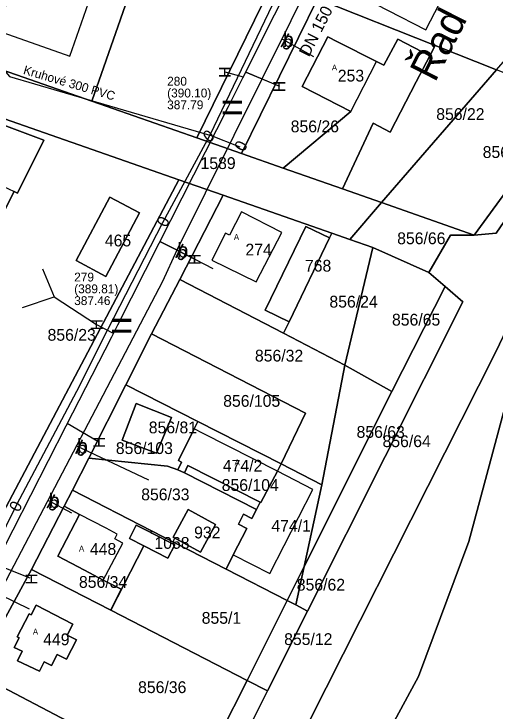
# Model space of a CAD drawing. Extents: x -564940 to -564406, y -1066466 to -1066072.
# Drawn here: x -564629.6 to -564548.1, y -1066405.8 to -1066287.6 of the extents above; entities that cross this region are included whole.
import ezdxf

# ---------------------------------------------------------------- set-up
doc = ezdxf.new("R2010")
doc.units = 0
for name, color, linetype in [('ft_g_5211', 7, 'Continuous'), ('ft_g_5411', 7, 'Continuous'), ('ft_g_6031', 7, 'Continuous'), ('ft_g_6040', 7, 'Continuous'), ('ft_g_6101', 7, 'Continuous'), ('ft_g_6101_ft_g_6101_da_6108_gtc_da_6108', 7, 'Continuous'), ('ft_g_6220', 7, 'Continuous'), ('ft_g_gps_soupe_pri', 7, 'Continuous'), ('ft_g_stoka', 7, 'Continuous'), ('ft_g_stoka_ft_g_stoka_da_popis_gtc_da_6004', 7, 'Continuous'), ('ft_g_vrad', 7, 'Continuous'), ('ft_g_vrad_ft_g_vrad_da_oznaceni_gtc_da_5095', 7, 'Continuous'), ('ft_g_vrad_ft_g_vrad_da_popis_gtc_da_5091', 7, 'Continuous'), ('ft_parcela_polygon', 7, 'Continuous'), ('ft_parcela_text', 7, 'Continuous'), ('ft_stavebni_objekt_bod', 7, 'Continuous'), ('ft_stavebni_objekt_polygon', 7, 'Continuous')]:
    doc.layers.add(name, color=color, linetype=linetype)

msp = doc.modelspace()

# ---------------------------------------------------------------- linework, layer by layer
at = {"layer": 'ft_g_5211'}
msp.add_line((-564623.9, -1066370.03), (-564619.9, -1066372.22), dxfattribs=at)
for points in [[(-564584.22, -1066291.86), (-564584.04, -1066291.96), (-564578.89, -1066294.81)], [(-564602.02, -1066327.63), (-564601.93, -1066327.68), (-564595.94, -1066330.79)], [(-564619.09, -1066360.83), (-564618.93, -1066360.91), (-564606.85, -1066366.6)], [(-564632.26, -1066385.97), (-564632.08, -1066386.06), (-564627.08, -1066388.46)]]:
    msp.add_lwpolyline(points, dxfattribs=at)
at = {"layer": 'ft_g_6040'}
for p, q in [((-564593.9, -1066297.43), (-564590.79, -1066298.28)), ((-564593.66, -1066297.5), (-564590.79, -1066298.28)), ((-564584.9, -1066299.77), (-564590.37, -1066297.46)), ((-564590.37, -1066297.46), (-564584.67, -1066299.87)), ((-564599.23, -1066329.07), (-564604.92, -1066326.21)), ((-564604.92, -1066326.21), (-564599.01, -1066329.18)), ((-564624.81, -1066330.81), (-564622.81, -1066335.57)), ((-564615.44, -1066360.1), (-564620.65, -1066357.07)), ((-564626.91, -1066383.3), (-564632.85, -1066380.93))]:
    msp.add_line(p, q, dxfattribs=at)
msp.add_lwpolyline([(-564628.19, -1066337.36), (-564622.81, -1066335.57), (-564615.63, -1066340.26), (-564612.81, -1066341.76)], dxfattribs=at)
at = {"layer": 'ft_g_stoka'}
msp.add_line((-564591.31, -1066310.22), (-564596.46, -1066308.15), dxfattribs=at)
for points in [[(-564553.41, -1066163.16), (-564553.48, -1066166.31), (-564548.89, -1066191.56), (-564549.63, -1066201.37), (-564551.36, -1066210.53), (-564553.55, -1066218.37), (-564556.52, -1066226.67), (-564558.83, -1066231.76), (-564567.86, -1066249.71), (-564582.71, -1066279.41), (-564586.53, -1066287.4), (-564596.46, -1066308.15), (-564604.5, -1066323.01), (-564613.83, -1066341.28), (-564619.05, -1066351.65), (-564629.23, -1066370.83), (-564638.15, -1066388.86), (-564652.7, -1066417.07), (-564664.74, -1066439.37), (-564677.25, -1066462.42), (-564679.03, -1066465.63)], [(-564574.81, -1066266.41), (-564590.9, -1066298.5), (-564591.23, -1066299.17), (-564593.34, -1066303.37)], [(-564636.43, -1066291.04), (-564630.4, -1066298.19), (-564613.43, -1066303.21), (-564596.46, -1066308.15)], [(-564593.34, -1066303.37), (-564605.08, -1066326.52), (-564612.1, -1066340.36)], [(-564612.1, -1066340.36), (-564613.14, -1066342.39), (-564620.85, -1066357.48), (-564632.88, -1066381), (-564633.79, -1066382.77)]]:
    msp.add_lwpolyline(points, dxfattribs=at)
at = {"layer": 'ft_g_vrad'}
msp.add_lwpolyline([(-564573.05, -1066269.82), (-564574.29, -1066272.32), (-564577.91, -1066279.06), (-564602.05, -1066327.68), (-564604.48, -1066332.96), (-564632.28, -1066386.02), (-564638.67, -1066398.97), (-564652.45, -1066423.53), (-564669.32, -1066454.46), (-564675.34, -1066465.63)], dxfattribs=at)
at = {"layer": 'ft_parcela_polygon'}
for points in [[(-564506.93, -1066072.02), (-564500.76, -1066095.62), (-564490.54, -1066131.29), (-564485.08, -1066150.07), (-564474.86, -1066195.24), (-564468.44, -1066228.77), (-564474.86, -1066248.97), (-564479.58, -1066256.49), (-564510.51, -1066292.89), (-564526.05, -1066309.43), (-564540.77, -1066329.78), (-564548.05, -1066345), (-564588.23, -1066424.58), (-564607.75, -1066462.97), (-564609.27, -1066465.63)], [(-564609.27, -1066465.63), (-564607.75, -1066462.97), (-564588.23, -1066424.58), (-564548.05, -1066345), (-564540.77, -1066329.78), (-564526.05, -1066309.43), (-564510.51, -1066292.89), (-564479.58, -1066256.49), (-564474.86, -1066248.97), (-564468.44, -1066228.77), (-564474.86, -1066195.24), (-564485.08, -1066150.07), (-564490.54, -1066131.29), (-564500.76, -1066095.62), (-564506.93, -1066072.02)], [(-564600.77, -1066465.63), (-564576.34, -1066428.17), (-564561.1, -1066399.98), (-564552.57, -1066377.06), (-564544.46, -1066346.76), (-564506.9, -1066296.8), (-564477.41, -1066257.73), (-564467.26, -1066239.44), (-564459.83, -1066220.33), (-564457.63, -1066204.67), (-564458.61, -1066193.4), (-564464.89, -1066162.6), (-564473.06, -1066136.49), (-564496.21, -1066076.34), (-564497.57, -1066072.02)], [(-564497.57, -1066072.02), (-564496.21, -1066076.34), (-564473.06, -1066136.49), (-564464.89, -1066162.6), (-564458.61, -1066193.4), (-564457.63, -1066204.67), (-564459.83, -1066220.33), (-564467.26, -1066239.44), (-564477.41, -1066257.73), (-564506.9, -1066296.8), (-564544.46, -1066346.76), (-564552.57, -1066377.06), (-564561.1, -1066399.98), (-564576.34, -1066428.17), (-564600.77, -1066465.63)], [(-564576.35, -1066263.01), (-564598.63, -1066308.62), (-564591.08, -1066311.25), (-564578.22, -1066284.98)], [(-564519.39, -1066285.88), (-564526.09, -1066292.91), (-564547.92, -1066324.79), (-564551.67, -1066325.09), (-564555.65, -1066325.14), (-564559.33, -1066331.43), (-564556.55, -1066333.83), (-564553.56, -1066336.41), (-564579.89, -1066388.86), (-564586.69, -1066402.39), (-564589.7, -1066408.39), (-564595.81, -1066420.56), (-564609.5, -1066447.82), (-564620.81, -1066465.63)], [(-564628.33, -1066465.63), (-564628.12, -1066465.26), (-564661.74, -1066446.92), (-564656.38, -1066437.43), (-564654.96, -1066434.92), (-564647.21, -1066420.91), (-564645.29, -1066417.18), (-564636.21, -1066399.34), (-564626.67, -1066381.79), (-564621.16, -1066371.09), (-564619.75, -1066368.35), (-564616.93, -1066362.92), (-564610.68, -1066350.52), (-564606.31, -1066341.84), (-564601.53, -1066332.64), (-564594.17, -1066318.35), (-564601.68, -1066315.73), (-564632.08, -1066373.21), (-564646.54, -1066402.48), (-564655.62, -1066419.11), (-564663.36, -1066435.96), (-564680.82, -1066465.63)], [(-564599.25, -1066418.75), (-564636.21, -1066399.34), (-564645.29, -1066417.18)]]:
    msp.add_lwpolyline(points, dxfattribs=at)
for points in [[(-564599.86, -1066254.8), (-564619.78, -1066247.85), (-564636.39, -1066295.43), (-564616.47, -1066302.39)], [(-564576.35, -1066263.01), (-564591.16, -1066257.84), (-564598.07, -1066255.43), (-564599.86, -1066254.8), (-564616.47, -1066302.39), (-564598.63, -1066308.62)], [(-564532.7, -1066279.57), (-564567.5, -1066263.08), (-564578.22, -1066284.98), (-564558.28, -1066292.94), (-564547.86, -1066297.09)], [(-564574.82, -1066292.32), (-564568.22, -1066295.67), (-564566.97, -1066296.31), (-564564.62, -1066291.86), (-564559.2, -1066294.72), (-564558.28, -1066292.94), (-564578.22, -1066284.98), (-564591.08, -1066311.25), (-564584.02, -1066313.73), (-564572.57, -1066304.16), (-564580.83, -1066299.88), (-564576.48, -1066291.48)], [(-564565.88, -1066307.63), (-564561.47, -1066299.1), (-564559.2, -1066294.72), (-564564.62, -1066291.86), (-564566.97, -1066296.31), (-564568.22, -1066295.67), (-564574.82, -1066292.32), (-564576.48, -1066291.48), (-564580.83, -1066299.88), (-564572.57, -1066304.16), (-564584.02, -1066313.73), (-564574, -1066317.25), (-564568.76, -1066306.14)], [(-564547.86, -1066297.09), (-564558.28, -1066292.94), (-564559.2, -1066294.72), (-564561.47, -1066299.1), (-564565.88, -1066307.63), (-564568.76, -1066306.14), (-564574, -1066317.25), (-564567.34, -1066319.59)], [(-564551.67, -1066325.09), (-564547.92, -1066324.79), (-564526.09, -1066292.91), (-564534.97, -1066302.23)], [(-564594.17, -1066318.35), (-564575.76, -1066324.78), (-564572.75, -1066325.83), (-564567.34, -1066319.59), (-564574, -1066317.25), (-564584.02, -1066313.73), (-564591.08, -1066311.25), (-564598.63, -1066308.62), (-564616.47, -1066302.39), (-564636.39, -1066295.43), (-564638.08, -1066303.01), (-564601.68, -1066315.73)], [(-564567.34, -1066319.59), (-564551.67, -1066325.09), (-564534.97, -1066302.23), (-564547.86, -1066297.09)], [(-564632.08, -1066373.21), (-564601.68, -1066315.73), (-564638.08, -1066303.01), (-564653.51, -1066333.95), (-564653.05, -1066334.19), (-564641.6, -1066311.25), (-564642, -1066311.05), (-564640.8, -1066308.69), (-564640.39, -1066308.89), (-564637.91, -1066304.04), (-564624.56, -1066308.99), (-564629.03, -1066318.02), (-564629.62, -1066317.73), (-564637.54, -1066333.25), (-564639.44, -1066332.28), (-564640.92, -1066335.16), (-564631.66, -1066339.9), (-564637.23, -1066350.79), (-564646.4, -1066346.09), (-564654.28, -1066361.05), (-564664.43, -1066355.85), (-564664.69, -1066356.49), (-564646.81, -1066365.78)], [(-564637.54, -1066333.25), (-564629.62, -1066317.73), (-564629.03, -1066318.02), (-564624.56, -1066308.99), (-564637.91, -1066304.04), (-564640.39, -1066308.89), (-564640.8, -1066308.69), (-564642, -1066311.05), (-564641.6, -1066311.25), (-564653.05, -1066334.19), (-564643.05, -1066339.41), (-564640.92, -1066335.16), (-564639.44, -1066332.28)], [(-564608.36, -1066321.32), (-564613.4, -1066318.65), (-564619.11, -1066329.44), (-564614.07, -1066332.1)], [(-564613.4, -1066318.65), (-564608.36, -1066321.32), (-564614.07, -1066332.1), (-564619.11, -1066329.44)], [(-564575.76, -1066324.78), (-564594.17, -1066318.35), (-564601.53, -1066332.64), (-564583.95, -1066341.75), (-564583.01, -1066339.8), (-564587.06, -1066337.85), (-564580.2, -1066323.63), (-564576.15, -1066325.59)], [(-564559.33, -1066331.43), (-564555.65, -1066325.14), (-564551.67, -1066325.09), (-564567.34, -1066319.59), (-564572.75, -1066325.83), (-564568.84, -1066327.19)], [(-564583.01, -1066339.8), (-564576.15, -1066325.59), (-564580.2, -1066323.63), (-564587.06, -1066337.85)], [(-564568.84, -1066327.19), (-564572.75, -1066325.83), (-564575.76, -1066324.78), (-564576.15, -1066325.59), (-564583.01, -1066339.8), (-564583.95, -1066341.75), (-564573.55, -1066347.14)], [(-564565.62, -1066351.65), (-564556.55, -1066333.83), (-564559.33, -1066331.43), (-564568.84, -1066327.19), (-564573.55, -1066347.14)], [(-564577.45, -1066367.43), (-564573.55, -1066347.14), (-564583.95, -1066341.75), (-564601.53, -1066332.64), (-564606.31, -1066341.84), (-564580.25, -1066355.33), (-564584.36, -1066363.92)], [(-564579.89, -1066388.86), (-564553.56, -1066336.41), (-564556.55, -1066333.83), (-564565.62, -1066351.65), (-564580.48, -1066381.33), (-564581.89, -1066387.83)], [(-564580.25, -1066355.33), (-564606.31, -1066341.84), (-564610.68, -1066350.52), (-564598.51, -1066356.71), (-564584.36, -1066363.92)], [(-564580.48, -1066381.33), (-564565.62, -1066351.65), (-564573.55, -1066347.14), (-564577.45, -1066367.43)], [(-564616.93, -1066362.92), (-564603.6, -1066364.28), (-564601.86, -1066364.89), (-564601.26, -1066363.61), (-564601.75, -1066363.35), (-564599.13, -1066357.97), (-564598.51, -1066356.71), (-564610.68, -1066350.52)], [(-564602.95, -1066356.03), (-564608.91, -1066353.67), (-564611.32, -1066359.88), (-564605.5, -1066362.08)], [(-564602.95, -1066356.03), (-564605.5, -1066362.08), (-564611.32, -1066359.88), (-564608.91, -1066353.67)], [(-564600.76, -1066365.41), (-564600.16, -1066364.18), (-564587.93, -1066370.39), (-564587.8, -1066370.46), (-564584.98, -1066365.14), (-564584.36, -1066363.92), (-564598.51, -1066356.71), (-564599.13, -1066357.97), (-564601.75, -1066363.35), (-564601.26, -1066363.61), (-564601.86, -1066364.89)], [(-564593.7, -1066381.75), (-564592.51, -1066379.32), (-564590.21, -1066374.87), (-564591.62, -1066374.15), (-564590.77, -1066372.42), (-564589.33, -1066373.14), (-564588.56, -1066371.62), (-564600.76, -1066365.41), (-564601.86, -1066364.89), (-564603.6, -1066364.28), (-564616.93, -1066362.92), (-564619.75, -1066368.35), (-564606.31, -1066375.27)], [(-564600.76, -1066365.41), (-564588.56, -1066371.62), (-564587.93, -1066370.39), (-564600.16, -1066364.18)], [(-564580.48, -1066381.33), (-564577.45, -1066367.43), (-564584.36, -1066363.92), (-564584.98, -1066365.14), (-564587.8, -1066370.46), (-564587.93, -1066370.39), (-564588.56, -1066371.62), (-564589.33, -1066373.14), (-564590.77, -1066372.42), (-564591.62, -1066374.15), (-564590.21, -1066374.87), (-564592.51, -1066379.32), (-564593.7, -1066381.75), (-564583.35, -1066387.08)], [(-564618.52, -1066372.47), (-564622.22, -1066379.56), (-564617.69, -1066381.92), (-564614.54, -1066383.64), (-564611.5, -1066385.15), (-564613.23, -1066388.71), (-564607.61, -1066377.81), (-564610.06, -1066376.55), (-564608.94, -1066374.27), (-564606.45, -1066375.55), (-564606.31, -1066375.27), (-564619.75, -1066368.35), (-564621.16, -1066371.09)], [(-564611.5, -1066385.15), (-564614.54, -1066383.64), (-564617.69, -1066381.92), (-564622.22, -1066379.56), (-564618.52, -1066372.47), (-564621.16, -1066371.09), (-564626.67, -1066381.79), (-564613.23, -1066388.71)], [(-564600.15, -1066371.65), (-564595.49, -1066374.21), (-564598.02, -1066378.87), (-564602.68, -1066376.33)], [(-564595.49, -1066374.21), (-564600.15, -1066371.65), (-564602.68, -1066376.33), (-564598.02, -1066378.87)], [(-564610.06, -1066376.55), (-564607.61, -1066377.81), (-564603.59, -1066379.92), (-564602.4, -1066377.65), (-564606.27, -1066375.64), (-564606.45, -1066375.55), (-564608.94, -1066374.27)], [(-564613.23, -1066388.71), (-564590.13, -1066400.62), (-564583.35, -1066387.08), (-564593.7, -1066381.75), (-564606.31, -1066375.27), (-564606.45, -1066375.55), (-564606.27, -1066375.64), (-564602.4, -1066377.65), (-564603.59, -1066379.92), (-564607.61, -1066377.81)], [(-564581.89, -1066387.83), (-564580.48, -1066381.33), (-564583.35, -1066387.08)], [(-564599.25, -1066418.75), (-564590.13, -1066400.62), (-564613.23, -1066388.71), (-564626.67, -1066381.79), (-564636.21, -1066399.34)], [(-564586.69, -1066402.39), (-564579.89, -1066388.86), (-564581.89, -1066387.83), (-564583.35, -1066387.08), (-564590.13, -1066400.62)], [(-564625.86, -1066387.84), (-564619.65, -1066391.06), (-564620.62, -1066392.93), (-564619.02, -1066393.76), (-564620.73, -1066397.04), (-564622.32, -1066396.21), (-564623.29, -1066398.07), (-564624.55, -1066397.46), (-564625.34, -1066399.08), (-564629.03, -1066397.3), (-564628.25, -1066395.68), (-564629.6, -1066395.02), (-564628.77, -1066393.42), (-564629.12, -1066393.24), (-564627.09, -1066389.34), (-564626.74, -1066389.52)], [(-564619.65, -1066391.06), (-564625.86, -1066387.84), (-564626.74, -1066389.52), (-564627.09, -1066389.34), (-564629.12, -1066393.24), (-564628.77, -1066393.42), (-564629.6, -1066395.02), (-564628.25, -1066395.68), (-564629.03, -1066397.3), (-564625.34, -1066399.08), (-564624.55, -1066397.46), (-564623.29, -1066398.07), (-564622.32, -1066396.21), (-564620.73, -1066397.04), (-564619.02, -1066393.76), (-564620.62, -1066392.93)], [(-564589.7, -1066408.39), (-564586.69, -1066402.39), (-564590.13, -1066400.62), (-564599.25, -1066418.75), (-564597.21, -1066419.82)]]:
    msp.add_lwpolyline(points, close=True, dxfattribs=at)
at = {"layer": 'ft_stavebni_objekt_polygon'}
for points in [[(-564632.53, -1066290.43), (-564620.16, -1066294.74), (-564616.2, -1066283.41), (-564615.26, -1066283.74), (-564610.48, -1066270.05), (-564611.43, -1066269.72), (-564607.47, -1066258.4), (-564619.84, -1066254.08), (-564622.28, -1066261.06), (-564617.93, -1066262.58), (-564619.45, -1066266.92), (-564620.39, -1066266.59), (-564625.17, -1066280.28), (-564624.23, -1066280.61), (-564625.75, -1066284.96), (-564630.09, -1066283.44)], [(-564572.59, -1066283.7), (-564559.85, -1066290.3), (-564555.2, -1066281.32), (-564559.44, -1066279.13), (-564556.54, -1066273.49), (-564565.02, -1066269.09)], [(-564580.83, -1066299.88), (-564572.57, -1066304.16), (-564568.22, -1066295.67), (-564574.82, -1066292.32), (-564576.48, -1066291.48)], [(-564653.05, -1066334.19), (-564643.05, -1066339.41), (-564640.92, -1066335.16), (-564639.44, -1066332.28), (-564631.51, -1066316.79), (-564629.62, -1066317.73), (-564629.03, -1066318.02), (-564624.56, -1066308.99), (-564637.91, -1066304.04), (-564640.39, -1066308.89), (-564640.8, -1066308.69), (-564642, -1066311.05), (-564641.6, -1066311.25)], [(-564593.77, -1066324.77), (-564596.14, -1066329.34), (-564588.6, -1066333.02), (-564584.28, -1066324.68), (-564591.1, -1066321.15), (-564593.14, -1066325.09)], [(-564601.26, -1066363.61), (-564601.86, -1066364.89), (-564600.76, -1066365.41), (-564600.16, -1066364.18), (-564587.93, -1066370.39), (-564587.8, -1066370.46), (-564584.98, -1066365.14), (-564597.6, -1066358.75), (-564599.13, -1066357.97), (-564601.75, -1066363.35)], [(-564584.98, -1066365.14), (-564587.8, -1066370.46), (-564587.93, -1066370.39), (-564588.56, -1066371.62), (-564589.33, -1066373.14), (-564590.77, -1066372.42), (-564591.62, -1066374.15), (-564590.21, -1066374.87), (-564592.51, -1066379.32), (-564586.28, -1066382.51), (-564579, -1066368.26)], [(-564618.52, -1066372.47), (-564622.22, -1066379.56), (-564617.69, -1066381.92), (-564614.54, -1066383.64), (-564611.18, -1066377.33), (-564612.54, -1066376.61), (-564612.13, -1066375.82), (-564613.99, -1066374.83)], [(-564629.6, -1066395.02), (-564628.25, -1066395.68), (-564629.03, -1066397.3), (-564625.34, -1066399.08), (-564624.55, -1066397.46), (-564623.29, -1066398.07), (-564622.32, -1066396.21), (-564620.73, -1066397.04), (-564619.02, -1066393.76), (-564620.62, -1066392.93), (-564619.65, -1066391.06), (-564625.86, -1066387.84), (-564626.74, -1066389.52), (-564627.09, -1066389.34), (-564629.12, -1066393.24), (-564628.77, -1066393.42)]]:
    msp.add_lwpolyline(points, close=True, dxfattribs=at)

# ---------------------------------------------------------------- texts
at = {"layer": 'ft_g_5411'}
for rotation, p in [(331.0661, (-564584.68, -1066293.04)), (332.5635, (-564602.54, -1066328.78)), (334.7701, (-564619.5, -1066362.02)), (331.3621, (-564624.33, -1066371.22))]:
    msp.add_text('b', height=2.5, rotation=rotation, dxfattribs=at).set_placement(p)
at = {"layer": 'ft_g_6031'}
for rotation, p in [(39.7008, (-564596.6, -1066309.54)), (243.1038, (-564591.75, -1066308.86)), (242.3189, (-564604.92, -1066321.68)), (62.7232, (-564628.81, -1066372.21))]:
    msp.add_text('0', height=2, rotation=rotation, dxfattribs=at).set_placement(p)
at = {"layer": 'ft_g_6101'}
for p in [(-564594.59, -1066305.87), (-564613.35, -1066342.86)]:
    msp.add_text('=', height=5, dxfattribs=at).set_placement(p)
at = {"layer": 'ft_g_6101_ft_g_6101_da_6108_gtc_da_6108'}
for s, p in [('280', (-564603.68, -1066299.76)), ('(390.10)', (-564603.68, -1066301.76)), ('387.79', (-564603.68, -1066303.76)), ('279', (-564619.43, -1066332.97)), ('(389.81)', (-564619.43, -1066334.97)), ('387.46', (-564619.43, -1066336.97))]:
    msp.add_text(s, height=1.5, dxfattribs=at).set_placement(p)
at = {"layer": 'ft_g_6220'}
for p in [(-564592.9, -1066298.43), (-564583.67, -1066300.87), (-564598.01, -1066330.18), (-564614.63, -1066341.26), (-564614.22, -1066361.23), (-564625.68, -1066384.39)]:
    msp.add_text('H', height=2, rotation=90, dxfattribs=at).set_placement(p)
at = {"layer": 'ft_g_gps_soupe_pri'}
for p in [(-564584.08, -1066293.21), (-564601.96, -1066328.93), (-564618.97, -1066362.16), (-564623.74, -1066371.39)]:
    msp.add_text('b', height=2.5, dxfattribs=at).set_placement(p)
at = {"layer": 'ft_g_stoka_ft_g_stoka_da_popis_gtc_da_6004'}
msp.add_text('Kruhové 300 PVC', height=1.5, rotation=343.5209, dxfattribs=at).set_placement((-564628.17, -1066297.74))
at = {"layer": 'ft_g_vrad_ft_g_vrad_da_oznaceni_gtc_da_5095'}
msp.add_text('Řad E1', height=5, rotation=63.1856, dxfattribs=at).set_placement((-564558.3, -1066299.35))
at = {"layer": 'ft_g_vrad_ft_g_vrad_da_popis_gtc_da_5091'}
msp.add_text('DN 150 LTH', height=2, rotation=63.1856, dxfattribs=at).set_placement((-564579.66, -1066295))
at = {"layer": 'ft_parcela_text'}
for s, p in [('253', (-564574.77, -1066299.06)), ('856/22', (-564558.09, -1066305.58)), ('856/26', (-564582.75, -1066307.67)), ('856/67', (-564550.22, -1066312.02)), ('1589', (-564598.03, -1066313.9)), ('856/66', (-564564.71, -1066326.65)), ('465', (-564614.24, -1066327.02)), ('274', (-564590.42, -1066328.56)), ('768', (-564580.34, -1066331.3)), ('856/24', (-564576.19, -1066337.4)), ('856/65', (-564565.59, -1066340.45)), ('856/23', (-564623.95, -1066343.02)), ('856/32', (-564588.81, -1066346.55)), ('856/105', (-564594.19, -1066354.22)), ('856/81', (-564606.8, -1066358.72)), ('856/63', (-564571.59, -1066359.49)), ('856/64', (-564567.19, -1066361.06)), ('856/103', (-564612.38, -1066362.23)), ('474/2', (-564594.25, -1066365.22)), ('856/104', (-564594.44, -1066368.49)), ('856/33', (-564608.08, -1066370.08)), ('474/1', (-564586.02, -1066375.41)), ('932', (-564599.11, -1066376.54)), ('1068', (-564605.84, -1066378.31)), ('448', (-564616.77, -1066379.34)), ('856/34', (-564618.63, -1066384.93)), ('856/62', (-564581.72, -1066385.39)), ('855/1', (-564597.83, -1066391.02)), ('449', (-564624.69, -1066394.66)), ('855/12', (-564583.86, -1066394.62)), ('856/36', (-564608.61, -1066402.77))]:
    msp.add_text(s, height=2, dxfattribs=at).set_placement(p)
at = {"layer": 'ft_stavebni_objekt_bod'}
for p in [(-564575.78, -1066297.19), (-564592.38, -1066325.94), (-564592.27, -1066364.15), (-564618.63, -1066378.77), (-564626.44, -1066392.86)]:
    msp.add_text('A', height=1, dxfattribs=at).set_placement(p)

doc.saveas('drawing.dxf')
